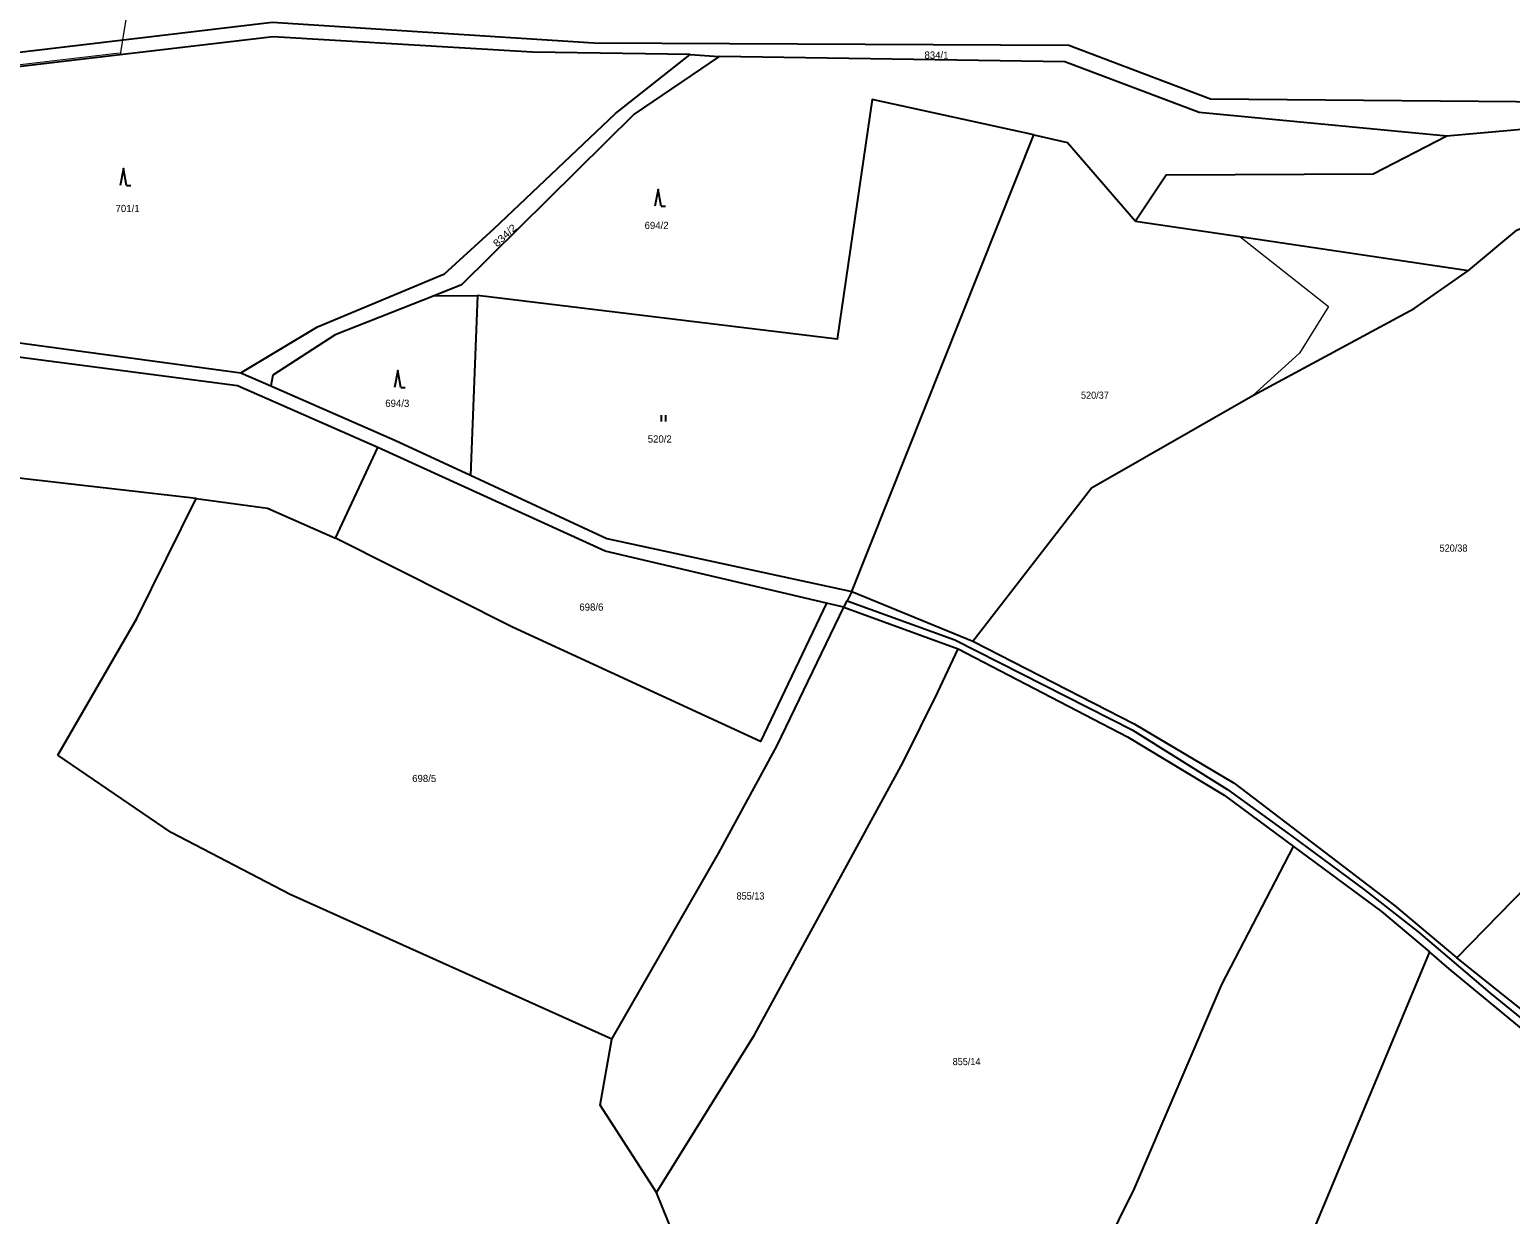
# Model space of a CAD drawing. Extents: x -687135 to -684370, y -1007309 to -1005782.
# Drawn here: x -686177.6 to -685826.9, y -1007050.2 to -1006769.6 of the extents above; entities that cross this region are included whole.
import ezdxf

# ---------------------------------------------------------------- set-up
doc = ezdxf.new("R2010")
doc.units = 0
doc.header["$LTSCALE"] = 0.68
for name, color, linetype, lineweight in [('1', 7, 'Continuous', 25), ('3', 7, 'Continuous', 25), ('4', 7, 'Continuous', 13)]:
    doc.layers.add(name, color=color, linetype=linetype, lineweight=lineweight)
doc.layers.add('2', color=7, linetype='Continuous')

msp = doc.modelspace()

# ---------------------------------------------------------------- linework, layer by layer
at = {"layer": '1'}
for p, q in [((-686021.13, -1006775.54), (-686014.25, -1006776)), ((-685800.81, -1006791.11), (-685841.9, -1006794.86)), ((-686081.83, -1006832.62), (-686071.55, -1006832.58)), ((-686071.55, -1006832.58), (-686073.22, -1006875.13)), ((-686127.59, -1006850.89), (-686120.49, -1006853.99)), ((-685984.74, -1006906.4), (-685983.96, -1006904.85)), ((-685982.86, -1006902.64), (-685983.96, -1006904.85)), ((-685982.86, -1006902.64), (-685954.18, -1006914.44)), ((-685984.74, -1006906.4), (-685957.64, -1006916.22))]:
    msp.add_line(p, q, dxfattribs=at)
for points in [[(-686343.59, -1006806.28), (-686314.7, -1006796.2), (-686276.55, -1006786.38), (-686120.2, -1006767.85), (-686044, -1006772.76), (-685931.45, -1006773.3), (-685897.9, -1006785.97), (-685807.25, -1006786.78), (-685789.93, -1006767.93)], [(-686021.13, -1006775.54), (-686058.53, -1006774.98), (-686119.92, -1006771.31), (-686274.47, -1006789.46), (-686315.96, -1006799.76), (-686336.89, -1006807.26)], [(-686127.59, -1006850.89), (-686109.43, -1006840.02), (-686079.38, -1006827.45), (-686067.67, -1006816.79), (-686038.82, -1006789.45), (-686021.13, -1006775.54)], [(-686014.25, -1006776), (-686034.44, -1006789.64), (-686075.34, -1006830.05), (-686081.83, -1006832.62)], [(-685841.9, -1006794.86), (-685900.61, -1006789.22), (-685932.44, -1006777.28), (-686014.25, -1006776)], [(-685939.73, -1006794.56), (-685978.01, -1006786.16), (-685986.3, -1006842.93), (-686071.55, -1006832.58)], [(-686138.15, -1006880.65), (-686198.14, -1006873.75), (-686240.45, -1006865.3), (-686273.26, -1006853.12), (-686304.83, -1006837.74), (-686346.13, -1006817.45), (-686350.01, -1006815.54), (-686351.3, -1006814.91), (-686354.61, -1006813.29), (-686373.72, -1006793.93)], [(-686073.22, -1006875.13), (-686040.89, -1006890.11), (-685982.86, -1006902.64), (-685939.73, -1006794.56)], [(-685939.73, -1006794.56), (-685931.76, -1006796.31), (-685915.64, -1006814.97)], [(-685841.9, -1006794.86), (-685859.37, -1006803.87), (-685908.41, -1006804.06), (-685915.64, -1006814.97)], [(-686336.89, -1006807.26), (-686294.33, -1006810.97), (-686266.73, -1006823.99), (-686222.56, -1006838.01), (-686127.59, -1006850.89)], [(-686095.17, -1006868.55), (-686128.41, -1006853.95), (-686222.64, -1006841.68), (-686270.59, -1006825.7), (-686295.89, -1006813.52), (-686342.75, -1006809.32)], [(-685836.8, -1006826.62), (-685825.36, -1006817.08), (-685807.49, -1006808.9), (-685765.63, -1006834.08), (-685752.72, -1006826.35)], [(-685915.64, -1006814.97), (-685890.95, -1006818.62), (-685836.8, -1006826.62)], [(-685954.18, -1006914.44), (-685926.08, -1006878.1), (-685887.85, -1006856.28), (-685849.62, -1006835.69), (-685836.8, -1006826.62)], [(-686081.83, -1006832.62), (-686105.21, -1006841.93), (-686119.98, -1006851.44), (-686120.49, -1006853.99)], [(-685839.55, -1006989.44), (-685809.54, -1006958.71), (-685775.47, -1006923.66), (-685749.74, -1006897.67), (-685716.52, -1006867.72), (-685765.63, -1006834.08)], [(-686120.49, -1006853.99), (-686091.09, -1006866.85), (-686073.22, -1006875.13)], [(-686138.15, -1006880.65), (-686121.26, -1006882.94), (-686105.18, -1006890), (-686095.17, -1006868.55)], [(-685988.89, -1006905.45), (-686041.28, -1006893.11), (-686095.17, -1006868.55)], [(-686170.94, -1006941.4), (-686152.19, -1006909.04), (-686138.15, -1006880.65)], [(-685988.89, -1006905.45), (-686004.5, -1006938.18), (-686063.27, -1006911.15), (-686105.18, -1006890)], [(-686039.71, -1007008.65), (-686014.4, -1006964.55), (-686001.09, -1006940.13), (-686000.54, -1006939.12), (-685984.74, -1006906.4), (-685988.89, -1006905.45)], [(-685983.96, -1006904.85), (-685958.47, -1006914.12), (-685916.47, -1006935.45), (-685893.9, -1006949.53), (-685878.72, -1006960.5), (-685861.45, -1006973.3), (-685848.73, -1006983.28), (-685831.73, -1006997.72), (-685812.81, -1007013.08), (-685779.43, -1007037.13), (-685751.37, -1007056.79), (-685721.37, -1007077.91), (-685689.18, -1007099.67), (-685648.4, -1007127.2)], [(-686029.1, -1007045), (-686005.94, -1007007.63), (-685970.69, -1006943.05), (-685962.46, -1006926.47), (-685957.64, -1006916.22)], [(-685957.64, -1006916.22), (-685917.52, -1006937.09), (-685894.63, -1006950.87), (-685878.25, -1006963.02)], [(-685954.18, -1006914.44), (-685916, -1006933.97), (-685892.33, -1006948.03), (-685854.3, -1006977.04), (-685839.55, -1006989.44)], [(-686039.71, -1007008.65), (-686115.91, -1006974.42), (-686144.09, -1006959.75), (-686170.94, -1006941.4)], [(-685955.32, -1007124.17), (-685941.96, -1007096.65), (-685915.9, -1007044), (-685895.22, -1006995.76), (-685878.25, -1006963.02)], [(-685878.25, -1006963.02), (-685857.42, -1006978.46), (-685846.06, -1006988.01)], [(-685846.06, -1006988.01), (-685879.53, -1007068.15), (-685897.56, -1007107.5), (-685916.46, -1007149.49)], [(-685721.07, -1007081.01), (-685819.28, -1007010.22), (-685841.33, -1006991.98), (-685846.06, -1006988.01)], [(-685778.52, -1007036.46), (-685802.3, -1007019.17), (-685839.55, -1006989.44)], [(-686024.97, -1007055.32), (-686029.1, -1007045), (-686042.48, -1007024.33), (-686039.71, -1007008.65)]]:
    msp.add_lwpolyline(points, dxfattribs=at)
at = {"layer": '3'}
for p, q in [((-686154.64, -1006806.5), (-686153.644, -1006806.5)), ((-686028.01, -1006811.46), (-686027.014, -1006811.46)), ((-686089.65, -1006854.33), (-686088.654, -1006854.33)), ((-686027.951, -1006862.41), (-686027.951, -1006860.91)), ((-686026.95, -1006862.41), (-686026.95, -1006860.91))]:
    msp.add_line(p, q, dxfattribs=at)
for points in [[(-686154.64, -1006806.5), (-686155.39, -1006802.5), (-686156.14, -1006806.5)], [(-686028.01, -1006811.46), (-686028.76, -1006807.46), (-686029.51, -1006811.46)], [(-686089.65, -1006854.33), (-686090.4, -1006850.33), (-686091.15, -1006854.33)]]:
    msp.add_lwpolyline(points, dxfattribs=at)
at = {"layer": '4'}
msp.add_line((-685890.95, -1006818.62), (-685869.96, -1006835.2), dxfattribs=at)
for points in [[(-686156.08, -1006775.56), (-686155.5, -1006772.03), (-686144.87, -1006707.46), (-686144.31, -1006704.06), (-686141.68, -1006688.12)], [(-686156.35, -1006775.23), (-686274.54, -1006789.06), (-686316.13, -1006799.39), (-686337.06, -1006806.91), (-686342.83, -1006809.05), (-686351.55, -1006814.56)], [(-685869.96, -1006835.2), (-685876.83, -1006846.23), (-685887.85, -1006856.28)]]:
    msp.add_lwpolyline(points, dxfattribs=at)

# ---------------------------------------------------------------- texts
at = {"layer": '2'}
for s, p in [('834/1', (-685965.65, -1006776.5)), ('701/1', (-686157.26, -1006812.82)), ('694/2', (-686031.95, -1006816.83)), ('694/3', (-686093.37, -1006858.95)), ('520/2', (-686031.2, -1006867.4)), ('698/6', (-686047.4, -1006907.2)), ('698/5', (-686087, -1006947.789))]:
    msp.add_text(s, height=1.7, dxfattribs=at).set_placement(p)
at = {"layer": '2', "width": 1.15}
msp.add_text('834/2', height=1.7, rotation=43, dxfattribs=at).set_placement((-686066.88, -1006821.201))
at = {"layer": '2', "width": 0.95}
for s, p in [('520/37', (-685928.58, -1006857.03)), ('520/38', (-685843.64, -1006893.24)), ('855/13', (-686010.17, -1006975.61)), ('855/14', (-685958.98, -1007014.82))]:
    msp.add_text(s, height=1.7, dxfattribs=at).set_placement(p)

doc.saveas('drawing.dxf')
